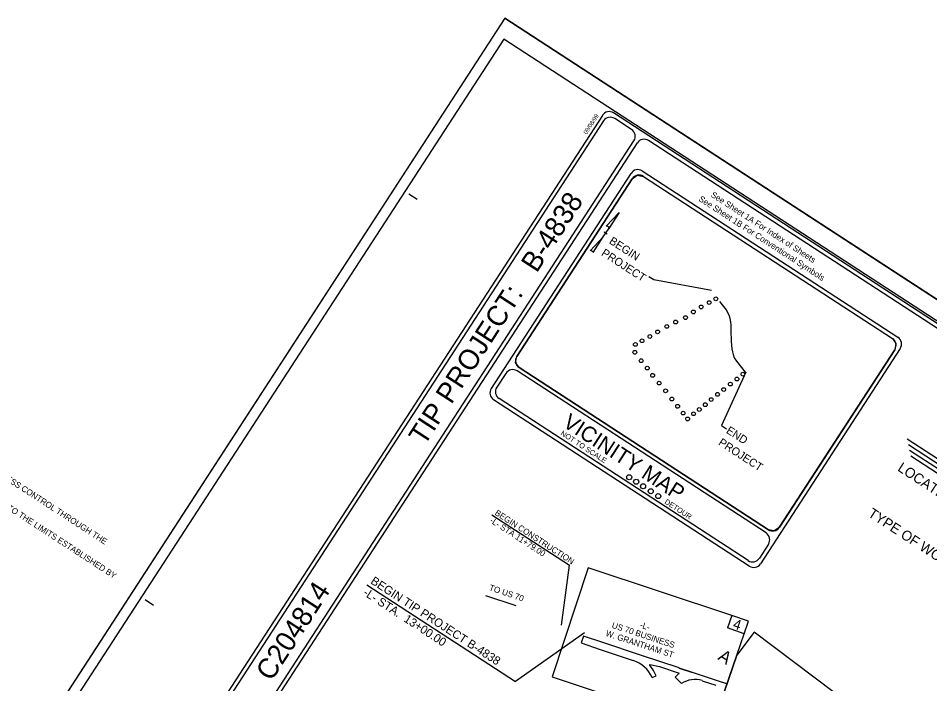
# Model space of a CAD drawing. Extents: x 2291197 to 2302790, y 592892 to 604246.
# Drawn here: x 2293776 to 2298300, y 600947 to 604246 of the extents above; entities that cross this region are included whole.
import ezdxf

# ---------------------------------------------------------------- set-up
doc = ezdxf.new("R2010")
doc.units = 0
for name, color, linetype in [('Default', 7, 'Continuous'), ('Old_Level_1', 7, 'Continuous'), ('Old_Level_12', 7, 'Continuous'), ('Old_Level_18', 7, 'Continuous'), ('Prop DSN Text', 7, 'Continuous'), ('Prop Horizontal Alignment Station Label', 7, 'Continuous'), ('Prop North Arrow for Plan Sheets CELL', 7, 'Continuous'), ('Prop Shade Light', 7, 'Continuous'), ('Scratch_Level_0', 7, 'Continuous'), ('Sheet Cutting Line CELL', 7, 'Continuous'), ('Sheet Data Field CELL', 7, 'Continuous'), ('Sheet Plot Border Inside CELL', 7, 'Continuous'), ('Sheet Plot Border Outside CELL', 7, 'Continuous'), ('Sheet Title CELL', 7, 'Continuous')]:
    doc.layers.add(name, color=color, linetype=linetype)

msp = doc.modelspace()

# ---------------------------------------------------------------- linework, layer by layer
at = {"layer": 'Default'}
msp.add_lwpolyline([(2298115.3, 602585.5), (2298115.3, 602585.8), (2298117, 602588.2)], dxfattribs=at)
at = {"layer": 'Old_Level_1'}
for p, q in [((2297553.2, 601720.9), (2298126.6, 602602.9)), ((2296262.5, 602513.8), (2297499.3, 601709.8))]:
    msp.add_line(p, q, dxfattribs=at)
msp.add_arc((2297520.3, 601744.3), 40.3, 238.6254, 324.6395, dxfattribs=at)
at = {"layer": 'Old_Level_18'}
for p, q in [((2296873.3, 603489), (2298141.8, 602664.4)), ((2296817.5, 603477.2), (2296123.9, 602410.3)), ((2296823.2, 603450.2), (2296250.8, 602569.6)), ((2296879, 603462), (2298114.8, 602658.7)), ((2298153.6, 602608.6), (2297460, 601541.7)), ((2298126.6, 602602.9), (2297554.1, 601722.3)), ((2296196.2, 602485.6), (2296151.1, 602416.3)), ((2297487.7, 601694.1), (2296251.9, 602497.4)), ((2297498.3, 601710.5), (2296262.6, 602513.8)), ((2297404.2, 601529.9), (2296135.7, 602354.5)), ((2297398.7, 601557.1), (2296162.9, 602360.5)), ((2297499.5, 601638.3), (2297454.5, 601569))]:
    msp.add_line(p, q, dxfattribs=at)
for centre, start, end in [((2296851.3, 603455.2), 56.9732, 146.9732), ((2296857, 603428.2), 56.9732, 146.9732), ((2298092.8, 602624.9), 326.9732, 56.9732), ((2298119.8, 602630.6), 326.9732, 56.9732), ((2296284.6, 602547.6), 146.9732, 236.9733), ((2296230, 602463.6), 56.9733, 146.9732), ((2296157.7, 602388.3), 146.9732, 236.9733), ((2296184.9, 602394.3), 146.9732, 236.9733), ((2297520.3, 601744.3), 236.9733, 326.9732), ((2297465.7, 601660.3), 326.9732, 56.9733), ((2297420.7, 601590.9), 236.9733, 326.9732), ((2297426.2, 601563.7), 236.9733, 326.9732)]:
    msp.add_arc(centre, 40.3, start, end, dxfattribs=at)
at = {"layer": 'Prop DSN Text'}
for p, q in [((2296096.1, 601383.5), (2296245.4, 601333.8)), ((2297317.2, 601285.5), (2297295.9, 601223.2)), ((2297379.1, 601194.7), (2297295.9, 601223.2))]:
    msp.add_line(p, q, dxfattribs=at)
for points in [[(2297217.6, 602895.7), (2296930.7, 602948.9), (2296906.5, 602964.6)], [(2297386.6, 602491.8), (2297266.8, 602227), (2297291.7, 602210.8)]]:
    msp.add_lwpolyline(points, dxfattribs=at)
for points in [[(2296425.8, 600981.2), (2297215.9, 600718.5), (2297379.1, 601194.7), (2297400.7, 601257.7), (2297317.2, 601285.5), (2296605.6, 601522.1)], [(2297342.9, 601088.9), (2297197.2, 600664), (2297631.7, 600336.7), (2298047, 600627.5), (2298059.7, 600644.4), (2298099.8, 600697.6), (2298027.9, 600751.8), (2297428.9, 601203.1)]]:
    msp.add_lwpolyline(points, close=True, dxfattribs=at)
at = {"layer": 'Prop Horizontal Alignment Station Label'}
for p, q in [((2296127.5, 601784.7), (2296511.5, 601535.1)), ((2296473.1, 601237.5), (2296511.5, 601535.1)), ((2295506.4, 601436.9), (2296244.2, 600957.3)), ((2296587.5, 601198.3), (2296244.2, 600957.3))]:
    msp.add_line(p, q, dxfattribs=at)
at = {"layer": 'Prop North Arrow for Plan Sheets CELL'}
for p, q in [((2296694.7, 603215.2), (2296758.4, 603283.4)), ((2296758.5, 603283.3), (2296706.9, 603203.9)), ((2296758.5, 603283.3), (2296758.4, 603283.4)), ((2296758.5, 603283.3), (2296758.4, 603283.4)), ((2296680.1, 603162.7), (2296708.4, 603206.2)), ((2296686, 603186.3), (2296685.9, 603186.4)), ((2296686, 603186.3), (2296699.3, 603177.6)), ((2296691.9, 603182.5), (2296686, 603186.3)), ((2296706.9, 603203.9), (2296708.3, 603206.2)), ((2296680.1, 603162.7), (2296615.2, 603093.3)), ((2296629.4, 603084.5), (2296680.1, 603162.7))]:
    msp.add_line(p, q, dxfattribs=at)
for centre, start_param, end_param in [((2296701.1, 603210), 0.216388, 2.908219), ((2296622, 603088.4), 0.201328, 3.141593)]:
    msp.add_ellipse(centre, major_axis=(6.99, -4.62), ratio=0.461098, start_param=start_param, end_param=end_param, dxfattribs=at)
at = {"layer": 'Prop Shade Light'}
for p, q in [((2296582.4, 601183.2), (2296570.7, 601149.2)), ((2296676.9, 601150.5), (2296582.4, 601183.2)), ((2296570.7, 601149.2), (2296665.3, 601116.4)), ((2296864.7, 601088.2), (2296676.9, 601150.5)), ((2296665.3, 601116.4), (2296829, 601061.9)), ((2297056.6, 601024.8), (2296864.7, 601088.2)), ((2296910.3, 601039.4), (2296910.9, 601041.3)), ((2296928.9, 601011.9), (2296910.3, 601039.4)), ((2296910.9, 601041.3), (2296958.3, 601032)), ((2296958.3, 601032), (2297056.7, 600999.5)), ((2297056.7, 600999.5), (2297036.5, 600978.6)), ((2297057.2, 601024.6), (2297056.6, 601024.8)), ((2297057.1, 601024.3), (2297122.9, 601002.4)), ((2297122.9, 601002.4), (2297057.1, 601024.3)), ((2297246.5, 600961.9), (2297123, 601002.8)), ((2296921.9, 600977.4), (2296942.8, 600985.6)), ((2297036.5, 600978.6), (2297068.7, 600947.6)), ((2297169.9, 600961.9), (2297238.9, 600939.1)), ((2297293.8, 600945.6), (2297246.5, 600961.9))]:
    msp.add_line(p, q, dxfattribs=at)
for points in [[(2297057.1, 601024.3), (2297057.2, 601024.6)], [(2297123, 601002.8), (2297122.9, 601002.4)]]:
    msp.add_lwpolyline(points, dxfattribs=at)
for centre, radius, start, end in [((2296780.1, 600914.9), 155, 23.7964, 71.6018), ((2296816.2, 600935.6), 136.1, 21.5519, 34.0968), ((2297133.7, 600852.8), 115, 71.6592, 124.4372)]:
    msp.add_arc(centre, radius, start, end, dxfattribs=at)
at = {"layer": 'Scratch_Level_0'}
msp.add_lwpolyline([(2296250.8, 602569.6), (2296823.2, 603450.2), (2296848.6, 603467.7), (2296879, 603462), (2298114.8, 602658.7), (2298132.2, 602633.2), (2298126.6, 602602.9), (2297553.2, 601720.9), (2297528.5, 601704.8), (2297499.3, 601709.8), (2296262.5, 602513.8), (2296245.1, 602539.2)], close=True, dxfattribs=at)
at = {"layer": 'Sheet Cutting Line CELL'}
for q in [(2293793.6, 600557.1), (2301839.2, 600574.8)]:
    msp.add_line((2296191.6, 604246.1), q, dxfattribs=at)
at = {"layer": 'Sheet Plot Border Inside CELL'}
msp.add_lwpolyline([(2293886.1, 600604), (2299475, 596970.9), (2301775.2, 600509.4), (2296186.3, 604142.5)], close=True, dxfattribs=at)
at = {"layer": 'Sheet Plot Border Outside CELL'}
msp.add_lwpolyline([(2301839.2, 600574.8), (2296191.6, 604246.1), (2293793.6, 600557.1), (2299441.2, 596885.8)], close=True, dxfattribs=at)
at = {"layer": 'Sheet Title CELL'}
for p, q in [((2294608.5, 600218.2), (2296832.2, 603638.9)), ((2295028.6, 600827.7), (2296849, 603628)), ((2295714.1, 603375.8), (2295756, 603348.5)), ((2295714.1, 603375.8), (2295756, 603348.5)), ((2298188.4, 602160.2), (2299617.1, 601231.5)), ((2298194.3, 602132.6), (2299589.4, 601225.6)), ((2298200.1, 602104.9), (2299561.7, 601219.8)), ((2298206, 602077.2), (2299534.1, 601213.9)), ((2294406, 601363.6), (2294448, 601336.3)), ((2294406, 601363.6), (2294448, 601336.3))]:
    msp.add_line(p, q, dxfattribs=at)
for points in [[(2296675.4, 603764.7), (2294429.9, 600310.4)], [(2296675.4, 603764.7), (2294429.9, 600310.4)], [(2301694.2, 600549.8), (2296730.7, 603776.5)], [(2296681.3, 603737), (2294457.6, 600316.3)], [(2296820.4, 603694.2), (2296736.6, 603748.8)], [(2301666.5, 600544), (2296904.3, 603639.7)], [(2297256.6, 602842.3), (2297289.9, 602800.1)], [(2297289.9, 602800.1), (2297302.4, 602775.5), (2297304.2, 602770), (2297307.3, 602758.7), (2297309.9, 602747.7), (2297310.9, 602741.9), (2297311.6, 602736.2), (2297312.2, 602729.4), (2297312.7, 602717.7), (2297312.9, 602712), (2297313.4, 602700.2), (2297314.5, 602642.9)], [(2297314.5, 602642.9), (2297318.4, 602606.5), (2297320.9, 602591.8), (2297323.9, 602579), (2297330.1, 602562.3), (2297340.5, 602546.4), (2297384.2, 602491)]]:
    msp.add_lwpolyline(points, dxfattribs=at)
for centre, radius in [((2297238.7, 602855.2), 9.38), ((2297165.5, 602814.9), 9.38), ((2297205.3, 602836.4), 9.38), ((2297088, 602761.8), 9.38), ((2297127, 602790.1), 9.38), ((2296995.4, 602718.2), 9.38), ((2297038.9, 602740.1), 9.38), ((2296911.3, 602668.5), 9.38), ((2296949.8, 602691), 9.38), ((2296839.3, 602629), 9.38), ((2296872.4, 602647.2), 9.38), ((2296836.7, 602589.9), 9.38), ((2296867.9, 602548.1), 9.38), ((2296898.4, 602511.6), 9.38), ((2296924.9, 602475.6), 9.38), ((2297372.9, 602481.5), 9.38), ((2296957.2, 602437.2), 9.38), ((2297310.5, 602432.3), 9.38), ((2297343.4, 602457.2), 9.38), ((2296989.2, 602398.7), 9.38), ((2297277.7, 602405.1), 9.38), ((2297020.1, 602358.3), 9.38), ((2297215.8, 602355.6), 9.38), ((2297247.2, 602381.5), 9.38), ((2297048.8, 602322.3), 9.38), ((2297156.5, 602306.6), 9.38), ((2297186.2, 602330), 9.38), ((2297076.1, 602288.6), 9.38), ((2297098.5, 602259.6), 9.38), ((2297128.1, 602285.2), 9.38), ((2296808.6, 601970.6), 12.5), ((2296843.1, 601948.2), 12.5), ((2296877.5, 601925.8), 12.5), ((2296915.3, 601901.3), 12.5), ((2296953, 601876.8), 12.5)]:
    msp.add_circle(centre, radius, dxfattribs=at)
for centre, start, end in [((2296709.1, 603743.1), 56.9737, 146.9737), ((2296714.9, 603715.4), 56.9737, 146.9737), ((2296798.8, 603660.9), 326.9737, 56.9737), ((2296882.6, 603606.4), 56.9737, 146.9737)]:
    msp.add_arc(centre, 40, start, end, dxfattribs=at)

# ---------------------------------------------------------------- texts
at = {"layer": 'Old_Level_1'}
for s, height, p in [('VICINITY MAP', 77.243, (2296473.8, 602225.7)), ('NOT TO SCALE', 26.019, (2296465.7, 602182.1))]:
    msp.add_text(s, height=height, rotation=326.9733, dxfattribs=at).set_placement(p)
at = {"layer": 'Old_Level_12'}
msp.add_text('See Sheet 1B For Conventional Symbols', height=30.247, rotation=326.9733, dxfattribs=at).set_placement((2297150.3, 603342.9))
at = {"layer": 'Prop DSN Text'}
for s, height, rotation, p in [('DETOUR', 26.02, 326.9737, (2296981.5, 601842.7)), ('TO US 70', 30, 341.3413, (2296110.6, 601411)), ('US 70 BUSINESS', 30, 341.8064, (2296719.5, 601224.6)), ('-L-', 30, 341.8064, (2296859, 601226.1)), ('4', 50, 341.6082, (2297319.4, 601222.8)), ('W. GRANTHAM ST', 30, 341.8064, (2296689, 601184.6)), ('A', 62.1, 326.9737, (2297244.9, 601069.6))]:
    msp.add_text(s, height=height, rotation=rotation, dxfattribs=at).set_placement(p)
at = {"layer": 'Prop Horizontal Alignment Station Label'}
for s, height, p in [('BEGIN CONSTRUCTION', 30, (2296138.6, 601786.4)), ('-L- STA 11+79.00', 30, (2296114.1, 601748.7)), ('BEGIN TIP PROJECT B-4838', 42, (2295521.6, 601446.2)), ('-L- STA.  13+00.00', 42, (2295484.4, 601389))]:
    msp.add_text(s, height=height, rotation=326.9737, dxfattribs=at).set_placement(p)
at = {"layer": 'Sheet Data Field CELL'}
for s, p in [('BEGIN', (2296705.4, 603132.3)), ('PROJECT', (2296666.8, 603073)), ('END', (2297286.3, 602192.8)), ('PROJECT', (2297247.7, 602133.5))]:
    msp.add_text(s, height=39.73, rotation=326.9737, dxfattribs=at).set_placement(p)
at = {"layer": 'Sheet Title CELL'}
for s, height, rotation, p in [('09/08/99', 21, 56.9737, (2296597.2, 603668.3)), ('B-4838  ', 100, 56.9737, (2296349.4, 602979.8)), ('See Sheet 1A For Index of Sheets', 30, 326.9737, (2297211.2, 603363.5)), ('TIP PROJECT:', 100, 56.9737, (2295792.2, 602122.7)), ('THIS MAINTAINS THE EXISTING ACCESS CONTROL THROUGH THE ', 29.801, 326.9737, (2293123.3, 602338.9)), ('CLEARING ON THIS PROJECT SHALL BE TO THE LIMITS ESTABLISHED BY ', 29.801, 326.9737, (2293059.4, 602240.6)), ('LOCATION: ', 50, 326.9737, (2298136.6, 602005.7)), ('TYPE OF WORK:', 50, 326.9737, (2297989.4, 601779.3)), ('C204814', 100, 56.9737, (2295032.9, 600954.6))]:
    msp.add_text(s, height=height, rotation=rotation, dxfattribs=at).set_placement(p)

doc.saveas('drawing.dxf')
